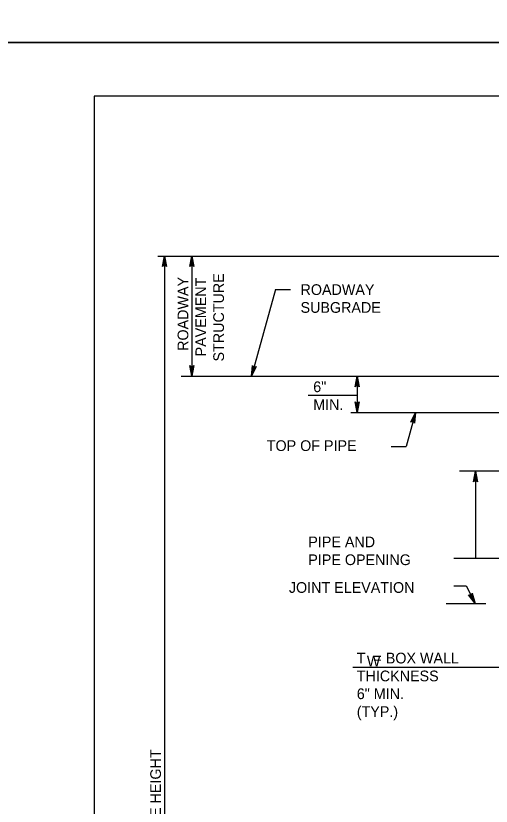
# Model space of a CAD drawing. Extents: x -6420 to 49575, y -4552 to 11624.
# Drawn here: x -3605 to -3168, y 3126 to 3853 of the extents above; entities that cross this region are included whole.
import ezdxf

# ---------------------------------------------------------------- set-up
doc = ezdxf.new("R2010")
doc.units = 0
doc.layers.add('1', color=7, linetype='Continuous')
doc.layers.add('PLT-BNDY', color=7, linetype='Continuous')

msp = doc.modelspace()

# ---------------------------------------------------------------- linework, layer by layer
at = {"layer": '1'}
for p, q in [((-3474.66, 3632.35), (-3154.36, 3632.35)), ((-3468.47, 3632.35), (-3468.47, 2586.52)), ((-3443.47, 3632.35), (-3443.47, 3521.89)), ((-3366.45, 3601.51), (-3388.5, 3521.89)), ((-3366.45, 3601.51), (-3352.51, 3601.51)), ((-3453.22, 3521.89), (-3154.36, 3521.89)), ((-3291.39, 3521.89), (-3291.39, 3488.56)), ((-3336.24, 3504.42), (-3291.39, 3504.42)), ((-3297.03, 3488.56), (-3077.72, 3488.56)), ((-3237.63, 3488.56), (-3246.35, 3457.07)), ((-3260.03, 3457.07), (-3246.35, 3457.07)), ((-2965.44, 3434.39), (-3197.25, 3434.39)), ((-3182.49, 3434.39), (-3182.49, 3354.31)), ((-3054.36, 3354.31), (-3202.34, 3354.31)), ((-3202.27, 3329.03), (-3190.95, 3329.03)), ((-3190.95, 3329.03), (-3182.68, 3312.91)), ((-3209.54, 3312.91), (-3172.86, 3312.91)), ((-3295.2, 3254.19), (-3099.74, 3254.19))]:
    msp.add_line(p, q, dxfattribs=at)
for points in [[(-954.49, 1929.01), (-954.49, 3779.41), (-3533.23, 3779.41), (-3533.23, 1929.01), (-954.49, 1929.01), (-954.49, 2015.49), (-1610.65, 2015.49), (-1610.65, 2227.69), (-954.49, 2227.69), (-954.49, 2322.72), (-1610.65, 2322.72), (-1610.65, 1929.01), (-1352.12, 1929.01), (-1352.12, 2015.49), (-1352.12, 1929.01), (-1099.49, 1929.01), (-1099.49, 2015.49), (-1099.49, 1975.09), (-954.49, 1975.09)], [(-3468.47, 3632.35), (-3466.63, 3622.56), (-3466.89, 3622.94), (-3467.15, 3623.32), (-3467.48, 3623.51), (-3467.81, 3623.71), (-3468.14, 3623.76), (-3468.47, 3623.82), (-3468.79, 3623.76), (-3469.12, 3623.71), (-3469.45, 3623.51), (-3469.78, 3623.32), (-3470.04, 3622.94), (-3470.3, 3622.56), (-3468.47, 3632.35), (-3470.04, 3622.94), (-3469.78, 3623.32), (-3468.47, 3632.35), (-3469.45, 3623.51), (-3469.12, 3623.71), (-3468.47, 3632.35), (-3468.79, 3623.76), (-3468.47, 3623.82), (-3468.47, 3632.35), (-3468.14, 3623.76), (-3467.81, 3623.71), (-3468.47, 3632.35), (-3467.48, 3623.51), (-3467.15, 3623.32), (-3468.47, 3632.35), (-3466.89, 3622.94)], [(-3443.47, 3632.35), (-3441.63, 3622.56), (-3442.15, 3623.32), (-3442.81, 3623.71), (-3443.47, 3623.82), (-3444.12, 3623.71), (-3444.78, 3623.32), (-3445.3, 3622.56), (-3443.47, 3632.35), (-3444.78, 3623.32), (-3444.12, 3623.71), (-3443.47, 3632.35), (-3443.47, 3623.82), (-3442.81, 3623.71), (-3443.47, 3632.35), (-3442.15, 3623.32)], [(-3443.47, 3521.89), (-3445.3, 3531.68), (-3444.78, 3530.92), (-3444.12, 3530.53), (-3443.47, 3530.42), (-3442.81, 3530.53), (-3442.15, 3530.92), (-3441.63, 3531.68), (-3443.47, 3521.89), (-3442.15, 3530.92), (-3442.81, 3530.53), (-3443.47, 3521.89), (-3443.47, 3530.42), (-3444.12, 3530.53), (-3443.47, 3521.89), (-3444.78, 3530.92)], [(-3388.5, 3521.89), (-3387.65, 3531.81), (-3387.35, 3530.94), (-3386.82, 3530.39), (-3386.22, 3530.11), (-3385.56, 3530.04), (-3384.82, 3530.24), (-3384.12, 3530.83), (-3388.5, 3521.89), (-3384.82, 3530.24), (-3385.56, 3530.04), (-3388.5, 3521.89), (-3386.22, 3530.11), (-3386.82, 3530.39), (-3388.5, 3521.89), (-3387.35, 3530.94)], [(-3291.39, 3521.89), (-3289.56, 3512.1), (-3289.82, 3512.48), (-3290.08, 3512.86), (-3290.41, 3513.05), (-3290.73, 3513.25), (-3291.06, 3513.3), (-3291.39, 3513.36), (-3291.72, 3513.3), (-3292.05, 3513.25), (-3292.38, 3513.05), (-3292.7, 3512.86), (-3292.96, 3512.48), (-3293.23, 3512.1), (-3291.39, 3521.89), (-3292.96, 3512.48), (-3292.7, 3512.86), (-3291.39, 3521.89), (-3292.38, 3513.05), (-3292.05, 3513.25), (-3291.39, 3521.89), (-3291.72, 3513.3), (-3291.39, 3513.36), (-3291.39, 3521.89), (-3291.06, 3513.3), (-3290.73, 3513.25), (-3291.39, 3521.89), (-3290.41, 3513.05), (-3290.08, 3512.86), (-3291.39, 3521.89), (-3289.82, 3512.48)], [(-3291.39, 3488.56), (-3293.23, 3498.34), (-3292.96, 3497.96), (-3292.7, 3497.59), (-3292.38, 3497.39), (-3292.05, 3497.2), (-3291.72, 3497.14), (-3291.39, 3497.09), (-3291.06, 3497.14), (-3290.73, 3497.2), (-3290.41, 3497.39), (-3290.08, 3497.59), (-3289.82, 3497.96), (-3289.56, 3498.34), (-3291.39, 3488.56), (-3289.82, 3497.96), (-3290.08, 3497.59), (-3291.39, 3488.56), (-3290.41, 3497.39), (-3290.73, 3497.2), (-3291.39, 3488.56), (-3291.06, 3497.14), (-3291.39, 3497.09), (-3291.39, 3488.56), (-3291.72, 3497.14), (-3292.05, 3497.2), (-3291.39, 3488.56), (-3292.38, 3497.39), (-3292.7, 3497.59), (-3291.39, 3488.56), (-3292.96, 3497.96)], [(-3237.63, 3488.56), (-3238.47, 3478.64), (-3238.77, 3479.5), (-3239.3, 3480.05), (-3239.9, 3480.34), (-3240.57, 3480.4), (-3241.3, 3480.2), (-3242.01, 3479.62), (-3237.63, 3488.56), (-3241.3, 3480.2), (-3240.57, 3480.4), (-3237.63, 3488.56), (-3239.9, 3480.34), (-3239.3, 3480.05), (-3237.63, 3488.56), (-3238.77, 3479.5)], [(-3182.49, 3434.39), (-3180.65, 3424.6), (-3180.91, 3424.98), (-3181.17, 3425.36), (-3181.5, 3425.55), (-3181.83, 3425.75), (-3182.16, 3425.8), (-3182.49, 3425.86), (-3182.81, 3425.8), (-3183.14, 3425.75), (-3183.47, 3425.55), (-3183.8, 3425.36), (-3184.06, 3424.98), (-3184.32, 3424.6), (-3182.49, 3434.39), (-3184.06, 3424.98), (-3183.8, 3425.36), (-3182.49, 3434.39), (-3183.47, 3425.55), (-3183.14, 3425.75), (-3182.49, 3434.39), (-3182.81, 3425.8), (-3182.49, 3425.86), (-3182.49, 3434.39), (-3182.16, 3425.8), (-3181.83, 3425.75), (-3182.49, 3434.39), (-3181.5, 3425.55), (-3181.17, 3425.36), (-3182.49, 3434.39), (-3180.91, 3424.98)], [(-3182.68, 3312.91), (-3188.78, 3320.78), (-3188.37, 3320.56), (-3187.97, 3320.35), (-3187.59, 3320.32), (-3187.21, 3320.3), (-3186.89, 3320.4), (-3186.57, 3320.5), (-3186.3, 3320.7), (-3186.04, 3320.9), (-3185.83, 3321.22), (-3185.63, 3321.55), (-3185.57, 3322), (-3185.51, 3322.45), (-3182.68, 3312.91), (-3185.57, 3322), (-3185.63, 3321.55), (-3182.68, 3312.91), (-3185.83, 3321.22), (-3186.04, 3320.9), (-3182.68, 3312.91), (-3186.3, 3320.7), (-3186.57, 3320.5), (-3182.68, 3312.91), (-3186.89, 3320.4), (-3187.21, 3320.3), (-3182.68, 3312.91), (-3187.59, 3320.32), (-3187.97, 3320.35), (-3182.68, 3312.91), (-3188.37, 3320.56)]]:
    msp.add_lwpolyline(points, dxfattribs=at)
at = {"layer": 'PLT-BNDY'}
for points in [[(-3661.18, 5777.44), (-901.99, 5777.44), (-901.99, 3828.62), (-3661.18, 3828.62)], [(-3661.18, 3828.62), (-901.99, 3828.62), (-901.99, 1879.8), (-3661.18, 1879.8)]]:
    msp.add_lwpolyline(points, close=True, dxfattribs=at)

# ---------------------------------------------------------------- texts
at = {"layer": '1'}
for s, height, p in [('ROADWAY', 9.843, (-3446.64, 3545.1)), ('STRUCTURE', 9.843, (-3413.83, 3535.34)), ('PAVEMENT', 9.843, (-3430.23, 3540.03)), ('H = OVERALL STRUCTURE HEIGHT', 9.8425, (-3471.8, 2955.24))]:
    msp.add_text(s, height=height, rotation=90, dxfattribs=at).set_placement(p)
for s, height, p in [('ROADWAY', 9.843, (-3343.4, 3596.52)), ('SUBGRADE', 9.843, (-3343.4, 3580.12)), ('6"', 9.843, (-3331.7, 3507.16)), ('MIN.', 9.843, (-3331.7, 3490.76)), ('TOP OF PIPE', 9.8425, (-3374.46, 3453.05)), ('  PIPE AND ', 9.8425, (-3343.56, 3364.53)), ('  PIPE OPENING', 9.8425, (-3343.56, 3348.13)), ('JOINT ELEVATION', 9.8425, (-3354.11, 3322.6)), ('T  = BOX WALL', 9.8425, (-3291.65, 3257.7)), ('W', 9.84, (-3282.34, 3254.9)), ('THICKNESS', 9.843, (-3291.65, 3241.29)), ('6" MIN.', 9.843, (-3291.65, 3224.89)), ('(TYP.)', 9.843, (-3291.65, 3208.48))]:
    msp.add_text(s, height=height, dxfattribs=at).set_placement(p)

doc.saveas('drawing.dxf')
